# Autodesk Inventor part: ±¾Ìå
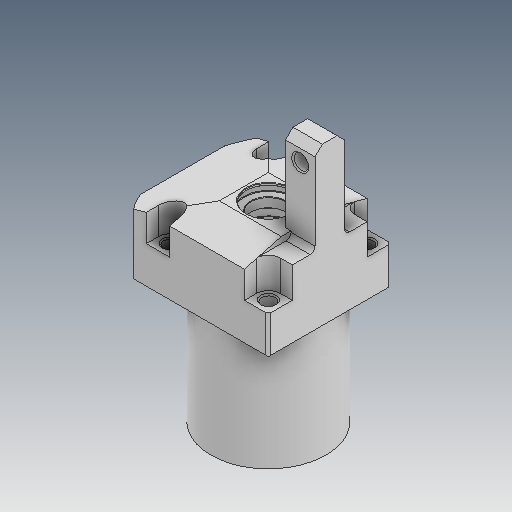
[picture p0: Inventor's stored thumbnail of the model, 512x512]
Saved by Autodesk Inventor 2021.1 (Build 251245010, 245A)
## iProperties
Created: 2015-08
Part Number: ±¾Ìå
Material: Ogólny
Document SubType Name: Modeling
Designer: user
Density: 1 g/cm^3
Appearance: Domyślna
Author: user
Revision Number: ÈÎºÎ
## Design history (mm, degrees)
feature "µ¹½Ç11"
node "Bryła1"
